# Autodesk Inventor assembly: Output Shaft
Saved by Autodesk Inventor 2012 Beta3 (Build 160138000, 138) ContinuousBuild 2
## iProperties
Created: 2011-01
Part Number: Output Shaft
Document SubType Name: Assembly
Designer: Beta-8540w
ClientObjectVersion: 1
Author: Beta-8540w
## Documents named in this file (2)
- C:\Inventor 2012 Essentials\Assemblies\Chapter 8\Design Accelerators\Shaft c8-01.iam
- C:\Inventor 2012 Essentials\Assemblies\Chapter 8\Design Accelerators\Shaft c8-01.ipt
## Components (1 placed, 1 different names)
1. Input Shaft:1
